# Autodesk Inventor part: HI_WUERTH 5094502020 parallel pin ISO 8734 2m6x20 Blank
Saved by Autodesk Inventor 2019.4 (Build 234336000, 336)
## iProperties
Created: 2021-06
Part Number: HI_WUERTH 5094502020 parallel pin ISO 8734 2m6x20 Blank
Material: Generic
Document SubType Name: Modeling
Designer: Administrator
Density: 1 g/cm^3
Appearance: Default
Title: HI_WUERTH 5094502020 parallel pin ISO 8734 2m6x20 Blank
Author: Administrator
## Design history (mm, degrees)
feature "Body1"
body "Solid1"
